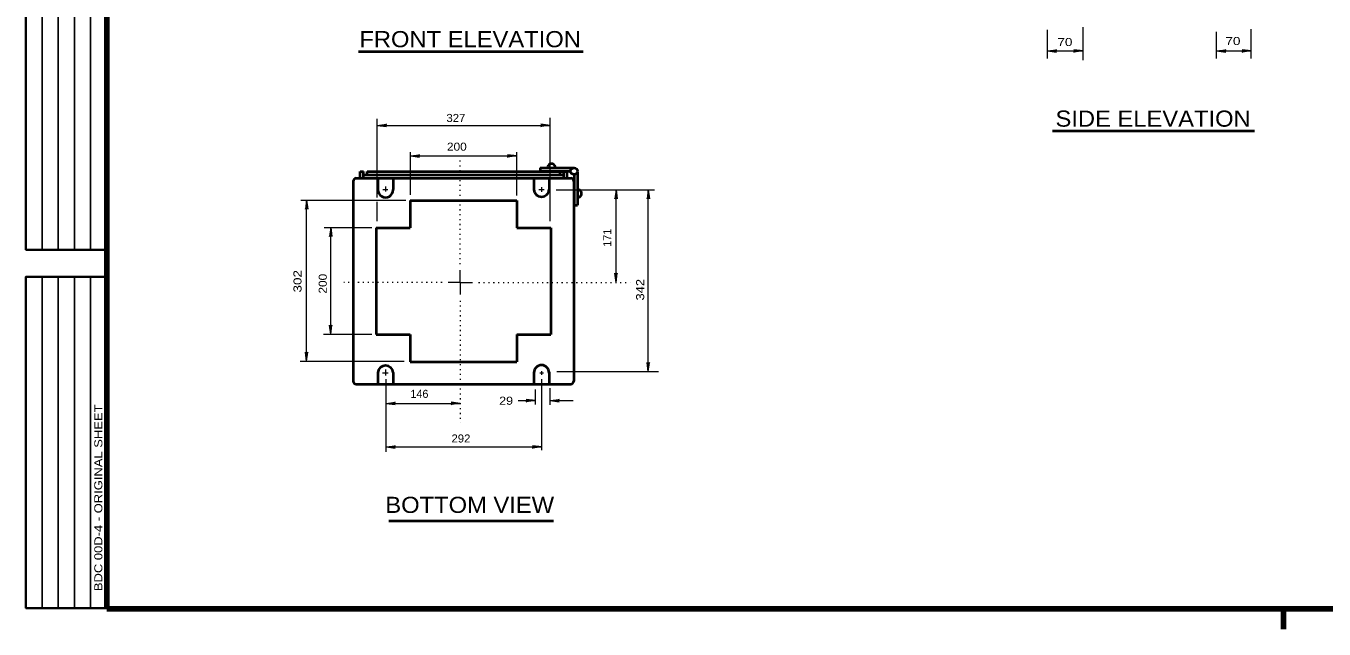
# Model space of a CAD drawing. Extents: x 312583 to 312853, y 144420 to 144585.
# Drawn here: x 312608.9 to 312731.2, y 144421.2 to 144478 of the extents above; entities that cross this region are included whole.
import ezdxf
from ezdxf.enums import TextEntityAlignment as Align

# ---------------------------------------------------------------- set-up
doc = ezdxf.new("R2010")
doc.units = 0
doc.header["$LTSCALE"] = 0.3
doc.linetypes.add('DOTTED', pattern=[1.5, 0.3, -1.2])
doc.layers.add('1', color=7, linetype='Continuous', lineweight=40)
doc.layers.add('2', color=7, linetype='Continuous', lineweight=13)

msp = doc.modelspace()

# ---------------------------------------------------------------- linework, layer by layer
at = {"layer": '1', "lineweight": 25}
for p, q in [((312610.4087, 144456.901), (312610.4087, 144488.1192)), ((312611.9315, 144456.901), (312611.9315, 144488.1192)), ((312613.4543, 144456.901), (312613.4543, 144488.1192)), ((312614.9772, 144456.901), (312614.9772, 144488.1192)), ((312610.4087, 144423.1446), (312610.4087, 144454.3629)), ((312611.9315, 144423.1446), (312611.9315, 144454.3629)), ((312613.4543, 144423.1446), (312613.4543, 144454.3629)), ((312614.9772, 144423.1446), (312614.9772, 144454.3629))]:
    msp.add_line(p, q, dxfattribs=at)
at = {"layer": '1'}
for p, q in [((312657.326, 144464.6268), (312660.477, 144464.6268)), ((312660.845, 144464.2281), (312660.845, 144461.1078)), ((312660.523, 144463.9981), (312660.523, 144461.1078)), ((312660.523, 144461.1078), (312660.845, 144461.1078))]:
    msp.add_line(p, q, dxfattribs=at)
at = {"layer": '1', "lineweight": 158}
for p, q in [((312616.5, 144423.0846), (312849, 144423.0846)), ((312727.35, 144421.1646), (312727.35, 144423.0846))]:
    msp.add_line(p, q, dxfattribs=at)
msp.add_lwpolyline([(312616.5, 144423.1446), (312616.5, 144585.0846), (312849, 144585.0846)], dxfattribs=at)
at = {"layer": '1', "lineweight": 35}
for points in [[(312616.5, 144456.901), (312608.8858, 144456.901), (312608.8858, 144488.1192), (312616.5, 144488.1192)], [(312616.5, 144423.1446), (312608.8858, 144423.1446), (312608.8858, 144454.3629), (312616.5, 144454.3629)]]:
    msp.add_lwpolyline(points, dxfattribs=at)
at = {"layer": '1'}
msp.add_lwpolyline([(312657.326, 144464.6268), (312657.326, 144464.3048), (312660.2163, 144464.3048)], dxfattribs=at)
msp.add_circle((312660.5192, 144464.3086), 0.3194, dxfattribs=at)
for centre, radius, start, end in [((312658.3853, 144464.6511), 0.3594, 359.38614, 180.61167), ((312639.9857, 144463.3887), 0.2614, 85.60018, 185.65208), ((312660.2279, 144463.3895), 0.2614, 355.60018, 95.65208), ((312660.8718, 144462.1977), 0.3594, 269.38614, 90.61167), ((312639.9852, 144444.5047), 0.2614, 175.60018, 275.65208), ((312660.2274, 144444.5056), 0.2614, 265.60018, 5.65208)]:
    msp.add_arc(centre, radius, start, end, dxfattribs=at)
at = {"layer": '2'}
for p, q in [((312708.4739, 144474.7643), (312708.4739, 144477.8846)), ((312724.3209, 144474.933), (312724.3209, 144477.7083)), ((312705.1083, 144474.933), (312705.1083, 144477.624)), ((312721.0473, 144474.933), (312721.0473, 144477.4553)), ((312705.1083, 144475.6428), (312705.9747, 144475.7501)), ((312705.1083, 144475.6428), (312705.9747, 144475.5355)), ((312705.1083, 144475.6428), (312708.4739, 144475.6428)), ((312705.9747, 144475.7501), (312705.6987, 144475.6428)), ((312705.9747, 144475.5355), (312705.6987, 144475.6428)), ((312707.6075, 144475.7501), (312707.8835, 144475.6428)), ((312708.4739, 144475.6428), (312707.6075, 144475.7501)), ((312707.6075, 144475.5355), (312707.8835, 144475.6428)), ((312708.4739, 144475.6428), (312707.6075, 144475.5355)), ((312721.0473, 144475.6428), (312721.9137, 144475.7501)), ((312721.0473, 144475.6428), (312721.9137, 144475.5355)), ((312721.0473, 144475.6428), (312724.3209, 144475.6428)), ((312721.9137, 144475.7501), (312721.6377, 144475.6428)), ((312721.9137, 144475.5355), (312721.6377, 144475.6428)), ((312723.4545, 144475.7501), (312723.7305, 144475.6428)), ((312724.3209, 144475.6428), (312723.4545, 144475.7501)), ((312723.4545, 144475.5355), (312723.7305, 144475.6428)), ((312724.3209, 144475.6428), (312723.4545, 144475.5355)), ((312641.9697, 144461.8208), (312641.9697, 144469.2421)), ((312658.2537, 144459.5975), (312658.2537, 144469.3418)), ((312641.9697, 144468.6211), (312642.836, 144468.7285)), ((312641.9697, 144468.6211), (312658.2537, 144468.6211)), ((312641.9697, 144468.6211), (312642.836, 144468.5138)), ((312642.836, 144468.7285), (312642.56, 144468.6211)), ((312642.836, 144468.5138), (312642.56, 144468.6211)), ((312657.3873, 144468.7285), (312657.6633, 144468.6211)), ((312658.2537, 144468.6211), (312657.3873, 144468.7285)), ((312657.3873, 144468.5138), (312657.6633, 144468.6211)), ((312658.2537, 144468.6211), (312657.3873, 144468.5138)), ((312645.0977, 144462.0738), (312645.0977, 144466.1141)), ((312645.0977, 144465.7538), (312645.964, 144465.8611)), ((312645.0977, 144465.7538), (312655.1257, 144465.7538)), ((312645.0977, 144465.7538), (312645.964, 144465.6465)), ((312645.964, 144465.8611), (312645.688, 144465.7538)), ((312645.964, 144465.6465), (312645.688, 144465.7538)), ((312654.2593, 144465.8611), (312654.5353, 144465.7538)), ((312655.1257, 144465.7538), (312654.2593, 144465.8611)), ((312654.2593, 144465.6465), (312654.5353, 144465.7538)), ((312655.1257, 144465.7538), (312654.2593, 144465.6465)), ((312655.1257, 144462.0048), (312655.1257, 144466.1141)), ((312642.514, 144462.5721), (312642.9663, 144462.5721)), ((312642.7593, 144462.8558), (312642.7593, 144462.3805)), ((312657.188, 144462.5721), (312657.7017, 144462.5721)), ((312657.4563, 144462.8021), (312657.4563, 144462.3728)), ((312658.8287, 144462.5645), (312668.0823, 144462.5645)), ((312664.479, 144462.5645), (312664.3717, 144461.6981)), ((312664.3717, 144461.6981), (312664.479, 144461.9741)), ((312664.479, 144453.8321), (312664.479, 144462.5645)), ((312664.479, 144462.5645), (312664.5863, 144461.6981)), ((312664.5863, 144461.6981), (312664.479, 144461.9741)), ((312667.5073, 144462.5645), (312667.4, 144461.6981)), ((312667.4, 144461.6981), (312667.5073, 144461.9741)), ((312667.5073, 144445.4295), (312667.5073, 144462.5645)), ((312667.5073, 144462.5645), (312667.6147, 144461.6981)), ((312667.6147, 144461.6981), (312667.5073, 144461.9741)), ((312634.7783, 144461.5831), (312644.6607, 144461.5831)), ((312635.3227, 144461.5831), (312635.2153, 144460.7168)), ((312635.2153, 144460.7168), (312635.3227, 144460.9928)), ((312635.3227, 144446.4031), (312635.3227, 144461.5831)), ((312635.3227, 144461.5831), (312635.43, 144460.7168)), ((312635.43, 144460.7168), (312635.3227, 144460.9928)), ((312641.9697, 144459.5975), (312641.9697, 144461.4145)), ((312636.9633, 144459.0148), (312641.4637, 144459.0148)), ((312637.5997, 144459.0148), (312637.4923, 144458.1485)), ((312637.4923, 144458.1485), (312637.5997, 144458.4245)), ((312637.5997, 144448.9485), (312637.5997, 144459.0148)), ((312637.5997, 144459.0148), (312637.707, 144458.1485)), ((312637.707, 144458.1485), (312637.5997, 144458.4245)), ((312649.805, 144453.8321), (312649.805, 144454.9821)), ((312664.3717, 144454.6985), (312664.479, 144454.4225)), ((312664.479, 144453.8321), (312664.3717, 144454.6985)), ((312664.5863, 144454.6985), (312664.479, 144454.4225)), ((312664.479, 144453.8321), (312664.5863, 144454.6985)), ((312649.805, 144453.8321), (312648.655, 144453.8321)), ((312649.805, 144453.8321), (312649.805, 144452.6821)), ((312649.805, 144453.8321), (312650.955, 144453.8321)), ((312637.4923, 144449.8148), (312637.5997, 144449.5388)), ((312637.5997, 144448.9485), (312637.4923, 144449.8148)), ((312637.707, 144449.8148), (312637.5997, 144449.5388)), ((312637.5997, 144448.9485), (312637.707, 144449.8148)), ((312636.925, 144448.9485), (312641.4637, 144448.9485)), ((312635.2153, 144447.2695), (312635.3227, 144446.9935)), ((312635.3227, 144446.4031), (312635.2153, 144447.2695)), ((312635.43, 144447.2695), (312635.3227, 144446.9935)), ((312635.3227, 144446.4031), (312635.43, 144447.2695)), ((312634.7093, 144446.4031), (312644.5303, 144446.4031)), ((312667.4, 144446.2958), (312667.5073, 144446.0198)), ((312667.5073, 144445.4295), (312667.4, 144446.2958)), ((312667.6147, 144446.2958), (312667.5073, 144446.0198)), ((312667.5073, 144445.4295), (312667.6147, 144446.2958)), ((312642.4603, 144445.3221), (312643.02, 144445.3221)), ((312642.7593, 144445.6365), (312642.7593, 144445.0538)), ((312642.813, 144437.8625), (312642.813, 144444.7088)), ((312657.2877, 144445.3221), (312657.648, 144445.3221)), ((312657.4563, 144445.4678), (312657.4563, 144445.1151)), ((312657.4717, 144438.0235), (312657.4717, 144444.7088)), ((312658.89, 144445.4295), (312668.4733, 144445.4295)), ((312656.889, 144442.3168), (312656.889, 144443.7351)), ((312658.2537, 144442.3015), (312658.2537, 144443.8655)), ((312642.813, 144442.4318), (312643.6793, 144442.5391)), ((312642.813, 144442.4318), (312649.805, 144442.4318)), ((312642.813, 144442.4318), (312643.6793, 144442.3245)), ((312643.6793, 144442.5391), (312643.4033, 144442.4318)), ((312643.6793, 144442.3245), (312643.4033, 144442.4318)), ((312648.9387, 144442.5391), (312649.2147, 144442.4318)), ((312649.805, 144442.4318), (312648.9387, 144442.5391)), ((312648.9387, 144442.3245), (312649.2147, 144442.4318)), ((312649.805, 144442.4318), (312648.9387, 144442.3245)), ((312655.2695, 144442.6925), (312656.889, 144442.6925)), ((312656.0227, 144442.7998), (312656.2987, 144442.6925)), ((312656.889, 144442.6925), (312656.0227, 144442.7998)), ((312656.0227, 144442.5851), (312656.2987, 144442.6925)), ((312656.889, 144442.6925), (312656.0227, 144442.5851)), ((312658.2537, 144442.6925), (312659.12, 144442.7998)), ((312658.2537, 144442.6925), (312659.12, 144442.5851)), ((312658.2537, 144442.6925), (312660.4428, 144442.6925)), ((312659.12, 144442.7998), (312658.844, 144442.6925)), ((312659.12, 144442.5851), (312658.844, 144442.6925)), ((312642.813, 144438.3225), (312643.6793, 144438.4298)), ((312642.813, 144438.3225), (312657.4717, 144438.3225)), ((312642.813, 144438.3225), (312643.6793, 144438.2151)), ((312643.6793, 144438.4298), (312643.4033, 144438.3225)), ((312643.6793, 144438.2151), (312643.4033, 144438.3225)), ((312656.6053, 144438.4298), (312656.8813, 144438.3225)), ((312657.4717, 144438.3225), (312656.6053, 144438.4298)), ((312656.6053, 144438.2151), (312656.8813, 144438.3225)), ((312657.4717, 144438.3225), (312656.6053, 144438.2151))]:
    msp.add_line(p, q, dxfattribs=at)
at = {"layer": '2', "lineweight": 40}
for p, q in [((312640.2238, 144475.5825), (312661.3827, 144475.5825)), ((312705.578, 144468.1096), (312724.6351, 144468.1096)), ((312640.3673, 144463.6531), (312640.3673, 144464.2895)), ((312640.3673, 144464.2895), (312640.6817, 144464.2895)), ((312640.6817, 144463.6301), (312640.6817, 144464.2895)), ((312641.019, 144463.9675), (312641.019, 144464.2895)), ((312641.019, 144464.2895), (312659.8483, 144464.2895)), ((312659.1813, 144464.2895), (312659.1813, 144463.9675)), ((312659.534, 144464.2895), (312659.534, 144463.6301)), ((312659.8483, 144464.2895), (312659.8483, 144463.6531)), ((312639.7233, 144463.4001), (312639.7233, 144444.5018)), ((312639.9763, 144463.6531), (312660.247, 144463.6531)), ((312640.6817, 144463.9675), (312659.534, 144463.9675)), ((312642.0387, 144463.6531), (312642.0387, 144462.5721)), ((312643.48, 144463.6531), (312643.48, 144462.5721)), ((312656.7357, 144463.6531), (312656.7357, 144462.5721)), ((312658.1693, 144463.6531), (312658.1693, 144462.5721)), ((312660.4923, 144463.3848), (312660.4923, 144444.5171)), ((312645.0747, 144461.5371), (312655.141, 144461.5371)), ((312645.0747, 144461.5371), (312645.0747, 144458.9765)), ((312655.141, 144461.5371), (312655.141, 144458.9765)), ((312641.8777, 144458.9765), (312641.8777, 144448.9178)), ((312641.8777, 144458.9765), (312645.0747, 144458.9765)), ((312655.141, 144458.9765), (312658.3303, 144458.9765)), ((312658.3303, 144458.9765), (312658.3303, 144448.9178)), ((312641.8777, 144448.9178), (312645.0747, 144448.9178)), ((312645.0747, 144448.9178), (312645.0747, 144446.3571)), ((312655.141, 144448.9178), (312658.3303, 144448.9178)), ((312655.141, 144448.9178), (312655.141, 144446.3571)), ((312645.0747, 144446.3571), (312655.141, 144446.3571)), ((312642.0463, 144445.3221), (312642.0463, 144444.2488)), ((312643.48, 144445.3375), (312643.48, 144444.2411)), ((312656.7357, 144445.3145), (312656.7357, 144444.2411)), ((312658.1693, 144445.4065), (312658.1693, 144444.2411)), ((312639.9763, 144444.2411), (312660.2547, 144444.2411)), ((312643.0637, 144431.3535), (312658.568, 144431.3535))]:
    msp.add_line(p, q, dxfattribs=at)
at = {"layer": '2', "linetype": 'DOTTED'}
for p, q in [((312649.805, 144455.5571), (312649.805, 144465.5238)), ((312648.08, 144453.8321), (312638.8263, 144453.8321)), ((312651.53, 144453.8321), (312665.813, 144453.8321)), ((312649.805, 144452.1071), (312649.805, 144440.6071))]:
    msp.add_line(p, q, dxfattribs=at)
at = {"layer": '2', "lineweight": 40}
for centre, start, end in [((312642.7581, 144462.5606), 179.08253, 0.72002), ((312657.4512, 144462.6181), 183.55302, 357.05546), ((312642.7606, 144445.2812), 3.46823, 176.7469), ((312657.4538, 144445.3132), 0, 179.59934)]:
    msp.add_arc(centre, 0.7188, start, end, dxfattribs=at)

# ---------------------------------------------------------------- texts
at = {"layer": '1', "width": 1.2}
msp.add_text('BDC 00D-4 - ORIGINAL SHEET', height=0.7614, rotation=90, dxfattribs=at).set_placement((312616.0832, 144424.7374))
at = {"layer": '2', "width": 1.1}
for s, p in [('FRONT ELEVATION', (312650.7282, 144475.9946)), ('SIDE ELEVATION', (312715.0679, 144468.5042)), ('BOTTOM VIEW', (312650.6902, 144432.1077))]:
    msp.add_text(s, height=1.52, dxfattribs=at).set_placement(p, align=Align.CENTER)
at = {"layer": '2'}
for s, width, p in [('70 ', 1.25, (312706.0533, 144476.1034)), ('70 ', 1.25, (312721.8827, 144476.1982)), ('327', 1.05, (312648.4985, 144468.9456)), ('200', 1.1, (312648.5456, 144466.2405)), ('29 ', 1.15, (312653.4676, 144442.2999)), ('292', 1.05, (312648.9712, 144438.7434))]:
    msp.add_text(s, height=0.76, dxfattribs=dict(at, width=width)).set_placement(p)
msp.add_text('171 ', height=0.76, rotation=90, dxfattribs=at).set_placement((312664.028, 144457.1891))
for s, width, p in [('302 ', 1.25, (312634.8461, 144452.8768)), ('200', 1.1, (312637.2229, 144452.7752)), ('342 ', 1.2, (312667.1273, 144452.1214))]:
    msp.add_text(s, height=0.76, rotation=90, dxfattribs=dict(at, width=width)).set_placement(p)
msp.add_text('146', height=0.76, dxfattribs=at).set_placement((312645.1052, 144442.9471))

doc.saveas('drawing.dxf')
